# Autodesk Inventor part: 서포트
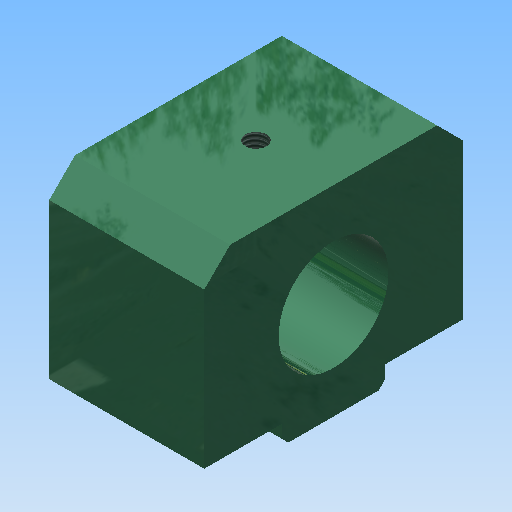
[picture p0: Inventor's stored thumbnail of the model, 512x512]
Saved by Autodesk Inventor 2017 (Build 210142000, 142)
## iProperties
Created: 2019-04
Part Number: 서포트
Material: 알루미늄 6061
Document SubType Name: Modeling
Designer: mduedu
Density: 1 g/cm^3
Appearance: 매끄러움 - 짙은 바다 녹색
Author: mduedu
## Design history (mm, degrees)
sketch "스케치1"
  geometry: L1 (3, 20)-(31, 20); L2 (31, 20)-(31, -20); L3 (31, -20)-(3, -20); L4 (0, -8)-(0, 8); L5 (0, 8)-(3, 8); L6 (3, 8)-(3, 20); L7 (0, 0)-(31, 0); L8 (0, -8)-(3, -8); L9 (3, -8)-(3, -20); 1 further point
  constraints: 18 end point, 3 symmetric about line, 2 horizontal, 2 midpoint, 2 parallel, 2 perpendicular, 1 coincident
  dimensions: "d3" = 31 distance between parallel lines of L4 L2; "d5" = 16 distance of L4.start L4.end; "d6" = 40 distance between parallel lines of L3 L1; "d7" = 3 distance between parallel lines of L4 L9
extrude "돌출1" new body sketch "스케치1" distance "d8" = 24; taper "d9" = 0 deg
chamfer "모따기1" distance "d10" = 4; stored, may be unused: second distance "d11" = 2, angle "d12" = 45 deg
chamfer "모따기2" distance "d13" = 1; stored, may be unused: second distance "d14" = 2, angle "d15" = 45 deg
sketch "스케치2"
  geometry: L1 (7, 0)-(-7, 0) reference; L2 (20, 3)-(8, 3) reference; 3 further points
  constraints: 1 midpoint, 1 vertical alignment
  dimensions: "d24" = 12 distance from line of point (0, 15) L2
hole "구멍1" sketch "스케치2" at (0, 15) diameter "d17" = 17; stored, may be unused: countersink angle "d21" = 90 deg, drill point angle "d23" = 118 deg; dims "d18" = 6, "d19" = 21, "d20" = 3, "d22" = 8
sketch "스케치3"
  geometry: L1 (0, 32)-(0, 0) reference; 3 further points
  constraints: 1 horizontal alignment, 1 midpoint
  dimensions: "d25" = 12 distance from line of point (12, 16) L1
hole "구멍2" sketch "스케치3" at (12, 16) diameter "d26" = 3.242; stored, may be unused: countersink angle "d30" = 90 deg, drill point angle "d32" = 118 deg; dims "d27" = 6, "d28" = 21, "d29" = 3, "d31" = 8
sketch "스케치4"
  geometry: L1 (0, -8)-(24, -8); L2 (24, 0.5)-(24, -16.5) reference; L3 (0, -28)-(0, -24) reference; 4 further points
  constraints: 2 end point, 2 symmetric about line, 1 horizontal, 1 horizontal alignment, 1 midpoint
  dimensions: "d33" = 6 distance from line of point (6, -22) L3; "d34" = 12 distance of point (18, -22) point (6, -22); "d35" = 28 distance of point (6, 6) point (6, -22); "d36" = 14 distance from line of point (6, -22) L1 (derived)
hole "구멍3" sketch "스케치4" at (6, -22), (18, -22), (18, 6), (6, 6) diameter "d37" = 3.242; stored, may be unused: countersink angle "d41" = 90 deg, drill point angle "d43" = 118 deg; dims "d38" = 9, "d39" = 21, "d40" = 3, "d42" = 11
node "솔리드1"
